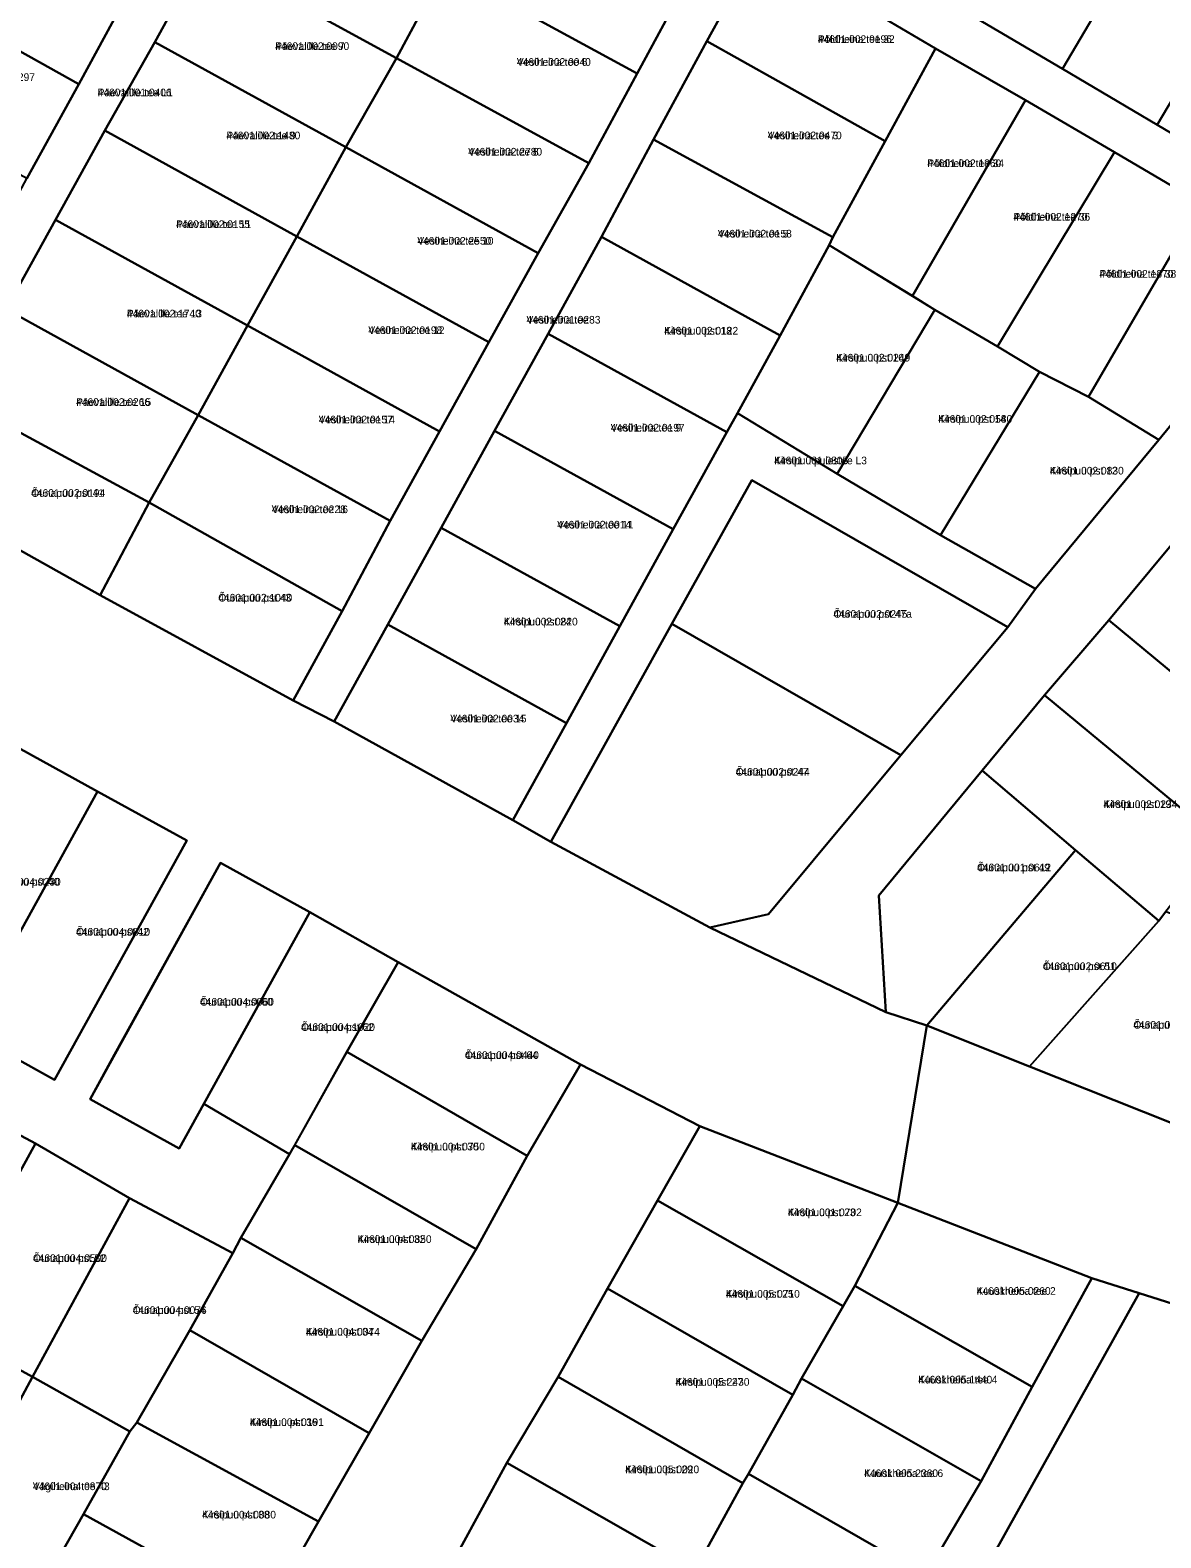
# Model space of a CAD drawing. Extents: x 551843 to 558501, y 6589003 to 6595718.
# Drawn here: x 552623.4 to 552845.1, y 6593188.1 to 6593483.8 of the extents above; entities that cross this region are included whole.
import ezdxf

# ---------------------------------------------------------------- set-up
doc = ezdxf.new("R2010")
doc.units = 0
for name, color, linetype in [('L_AADRESS', 7, 'Continuous'), ('PIIR', 7, 'Continuous'), ('TUNNUS', 7, 'Continuous')]:
    doc.layers.add(name, color=color, linetype=linetype)

msp = doc.modelspace()

# ---------------------------------------------------------------- linework, layer by layer
at = {"layer": 'PIIR'}
for points in [[(552660.92, 6593544.41), (552681.3, 6593543.01), (552676.56, 6593534.11), (552667.17, 6593516.83), (552657.46, 6593498.94), (552647.84, 6593481.41), (552638.03, 6593464.12), (552628.37, 6593446.6), (552618.71, 6593429.08), (552609.04, 6593411.57), (552599.39, 6593394.06), (552591.99, 6593398.44), (552602.33, 6593417.19), (552612.65, 6593435.92), (552622.77, 6593454.66), (552632.95, 6593473.18), (552643.15, 6593492.04), (552653.7, 6593510.58), (552664.72, 6593530.92)], [(552846.41, 6593511.09), (552825.8, 6593476.22), (552806.82, 6593487.36), (552827.29, 6593521.85)], [(552667.17, 6593516.83), (552704.66, 6593495.87), (552695.23, 6593478.3), (552657.46, 6593498.94)], [(552607.91, 6593511.51), (552643.15, 6593492.04), (552632.95, 6593473.18), (552597.6, 6593492.97)], [(552742.42, 6593475.29), (552704.66, 6593495.87), (552714.46, 6593513.43), (552751.91, 6593492.86)], [(552865.01, 6593500.1), (552844.4, 6593465.23), (552825.8, 6593476.22), (552846.41, 6593511.09), (552847.08, 6593510.72)], [(552751.91, 6593492.86), (552758.88, 6593505.25), (552766.49, 6593500.52), (552756.06, 6593481.6), (552745.63, 6593462.31), (552735.44, 6593443.26), (552724.97, 6593424.24), (552714.47, 6593405.23), (552703.99, 6593386.21), (552693.51, 6593367.19), (552683.03, 6593348.18), (552674.95, 6593352.34), (552684.6, 6593369.82), (552693.98, 6593387.52), (552703.66, 6593405.04), (552713.32, 6593422.59), (552723.01, 6593440.07), (552732.91, 6593457.71), (552742.42, 6593475.29)], [(552756.06, 6593481.6), (552766.49, 6593500.52), (552800.91, 6593480.16), (552791.04, 6593462.01)], [(552844.4, 6593465.23), (552865.01, 6593500.1), (552883.61, 6593489.1), (552862.75, 6593454.33)], [(552657.46, 6593498.94), (552695.23, 6593478.3), (552685.33, 6593460.85), (552647.84, 6593481.41)], [(552742.42, 6593475.29), (552732.91, 6593457.71), (552695.23, 6593478.3), (552704.66, 6593495.87)], [(552597.6, 6593492.97), (552632.95, 6593473.18), (552622.77, 6593454.66), (552587.23, 6593474.17), (552592.89, 6593484.72)], [(552745.63, 6593462.31), (552756.06, 6593481.6), (552791.04, 6593462.01), (552780.81, 6593443.17)], [(552685.33, 6593460.85), (552675.66, 6593443.34), (552638.03, 6593464.12), (552647.84, 6593481.41)], [(552780.03, 6593441.62), (552780.81, 6593443.17), (552791.04, 6593462.01), (552800.91, 6593480.16), (552818.57, 6593470.07), (552796.41, 6593431.66)], [(552695.23, 6593478.3), (552732.91, 6593457.71), (552723.01, 6593440.07), (552685.33, 6593460.85)], [(552835.98, 6593459.84), (552813.09, 6593421.74), (552800.81, 6593428.95), (552796.41, 6593431.66), (552818.57, 6593470.07)], [(552638.03, 6593464.12), (552675.66, 6593443.34), (552666.01, 6593425.83), (552628.37, 6593446.6)], [(552723.01, 6593440.07), (552713.32, 6593422.59), (552675.66, 6593443.34), (552685.33, 6593460.85)], [(552745.63, 6593462.31), (552780.81, 6593443.17), (552780.03, 6593441.62), (552770.48, 6593423.92), (552735.44, 6593443.26)], [(552853.01, 6593449.87), (552830.93, 6593411.86), (552821.29, 6593416.75), (552813.09, 6593421.74), (552835.98, 6593459.84)], [(552873.04, 6593438.03), (552844.73, 6593403.44), (552830.93, 6593411.86), (552853.01, 6593449.87)], [(552628.37, 6593446.6), (552666.01, 6593425.83), (552656.34, 6593408.3), (552618.71, 6593429.08)], [(552713.32, 6593422.59), (552703.66, 6593405.04), (552666.01, 6593425.83), (552675.66, 6593443.34)], [(552770.48, 6593423.92), (552762.08, 6593408.7), (552759.99, 6593404.91), (552724.97, 6593424.24), (552735.44, 6593443.26)], [(552781.62, 6593396.74), (552762.08, 6593408.7), (552770.48, 6593423.92), (552780.03, 6593441.62), (552800.81, 6593428.95)], [(552656.34, 6593408.3), (552646.71, 6593391.12), (552609.04, 6593411.57), (552618.71, 6593429.08)], [(552781.62, 6593396.74), (552800.81, 6593428.95), (552813.09, 6593421.74), (552821.29, 6593416.75), (552801.92, 6593384.73)], [(552693.98, 6593387.52), (552656.34, 6593408.3), (552666.01, 6593425.83), (552703.66, 6593405.04)], [(552714.47, 6593405.23), (552724.97, 6593424.24), (552759.99, 6593404.91), (552749.49, 6593385.9)], [(552820.54, 6593374.19), (552801.92, 6593384.73), (552821.29, 6593416.75), (552830.93, 6593411.86), (552844.73, 6593403.44)], [(552599.39, 6593394.06), (552609.04, 6593411.57), (552646.71, 6593391.12), (552637.14, 6593372.95)], [(552656.34, 6593408.3), (552693.98, 6593387.52), (552684.6, 6593369.82), (552646.71, 6593391.12)], [(552759.99, 6593404.91), (552762.08, 6593408.7), (552781.62, 6593396.74), (552801.92, 6593384.73), (552820.54, 6593374.19), (552815.08, 6593366.72), (552764.9, 6593395.51), (552749.24, 6593367.35), (552725.49, 6593324.63), (552718.05, 6593328.85), (552728.54, 6593347.87), (552739.03, 6593366.88), (552749.49, 6593385.9)], [(552714.47, 6593405.23), (552749.49, 6593385.9), (552739.03, 6593366.88), (552703.99, 6593386.21)], [(552764.9, 6593395.51), (552815.08, 6593366.72), (552794.14, 6593341.59), (552749.24, 6593367.35)], [(552684.6, 6593369.82), (552674.95, 6593352.34), (552637.14, 6593372.95), (552646.71, 6593391.12)], [(552703.99, 6593386.21), (552739.03, 6593366.88), (552728.54, 6593347.87), (552693.51, 6593367.19)], [(552881.45, 6593353.97), (552877.67, 6593349.36), (552869.6, 6593339.34), (552834.92, 6593368.05), (552847.11, 6593382.78)], [(552728.54, 6593347.87), (552718.05, 6593328.85), (552683.03, 6593348.18), (552693.51, 6593367.19)], [(552749.24, 6593367.35), (552794.14, 6593341.59), (552768.15, 6593310.4), (552756.64, 6593307.81), (552725.49, 6593324.63)], [(552834.92, 6593368.05), (552869.6, 6593339.34), (552856.94, 6593324.66), (552822.25, 6593353.36)], [(552810.06, 6593338.62), (552822.25, 6593353.36), (552856.94, 6593324.66), (552846.1, 6593310.91), (552844.71, 6593309.11), (552828.37, 6593322.95)], [(552608.23, 6593325.27), (552619.09, 6593344.16), (552636.6, 6593334.49), (552610.7, 6593287.57), (552593.19, 6593297.23), (552598.46, 6593306.95)], [(552799.23, 6593288.6), (552791.2, 6593291.19), (552789.78, 6593314.1), (552810.06, 6593338.62), (552828.37, 6593322.95)], [(552610.7, 6593287.57), (552636.6, 6593334.49), (552654.11, 6593324.83), (552628.2, 6593277.92)], [(552799.23, 6593288.6), (552828.37, 6593322.95), (552844.71, 6593309.11), (552819.32, 6593280.52)], [(552678.26, 6593310.83), (552657.48, 6593273.2), (552652.65, 6593264.45), (552635.14, 6593274.12), (552639.97, 6593282.86), (552660.75, 6593320.5)], [(552695.55, 6593301), (552685.47, 6593283.42), (552674.28, 6593263.36), (552657.48, 6593273.2), (552678.26, 6593310.83)], [(552819.32, 6593280.52), (552844.71, 6593309.11), (552846.1, 6593310.91), (552860.07, 6593305.95), (552847.12, 6593269.52)], [(552731.28, 6593280.95), (552720.86, 6593263.03), (552685.47, 6593283.42), (552695.55, 6593301)], [(552685.47, 6593283.42), (552720.86, 6593263.03), (552710.85, 6593244.74), (552675.28, 6593265.11)], [(552624.44, 6593265.44), (552605.01, 6593230), (552586.29, 6593240.49), (552605.17, 6593275.73)], [(552785.08, 6593237.53), (552782.8, 6593233.53), (552746.39, 6593254.25), (552754.7, 6593268.85), (552793.5, 6593253.79)], [(552605.01, 6593230), (552624.44, 6593265.44), (552642.91, 6593254.69), (552623.85, 6593219.65)], [(552675.28, 6593265.11), (552710.85, 6593244.74), (552700.22, 6593226.77), (552664.71, 6593246.94), (552674.28, 6593263.36)], [(552642.91, 6593254.69), (552663.17, 6593243.91), (552654.68, 6593228.8), (552644.33, 6593210.72), (552642.95, 6593208.95), (552623.85, 6593219.65)], [(552736.63, 6593237.01), (552746.39, 6593254.25), (552782.8, 6593233.53), (552774.63, 6593219.35), (552772.92, 6593216.16)], [(552785.08, 6593237.53), (552793.5, 6593253.79), (552831.56, 6593239.02), (552819.89, 6593217.73)], [(552664.71, 6593246.94), (552700.22, 6593226.77), (552689.9, 6593208.6), (552654.68, 6593228.8), (552663.17, 6593243.91)], [(552736.63, 6593237.01), (552772.92, 6593216.16), (552764.24, 6593200.63), (552763.13, 6593198.84), (552726.95, 6593219.7)], [(552774.63, 6593219.35), (552782.8, 6593233.53), (552785.08, 6593237.53), (552819.89, 6593217.73), (552809.88, 6593199.24)], [(552807.46, 6593176.14), (552840.87, 6593236.09), (552974.33, 6593193.77)], [(552604.93, 6593184.4), (552585.36, 6593194.77), (552605.01, 6593230), (552623.85, 6593219.65)], [(552654.68, 6593228.8), (552689.9, 6593208.6), (552679.92, 6593191.28), (552644.33, 6593210.72)], [(552604.93, 6593184.4), (552623.85, 6593219.65), (552642.95, 6593208.95), (552633.87, 6593192.76), (552623.45, 6593174.45)], [(552763.13, 6593198.84), (552754.26, 6593182.64), (552753.54, 6593181.86), (552716.86, 6593202.78), (552726.95, 6593219.7)], [(552772.92, 6593216.16), (552774.63, 6593219.35), (552809.88, 6593199.24), (552798.93, 6593180.69), (552764.24, 6593200.63)], [(552644.33, 6593210.72), (552679.92, 6593191.28), (552669.58, 6593173.09), (552633.87, 6593192.76), (552642.95, 6593208.95)], [(552716.86, 6593202.78), (552753.54, 6593181.86), (552743.84, 6593164.53), (552707.32, 6593185.27)], [(552763.13, 6593198.84), (552764.24, 6593200.63), (552798.93, 6593180.69), (552788.77, 6593162.59), (552754.26, 6593182.64)], [(552659.45, 6593154.58), (552623.45, 6593174.45), (552633.87, 6593192.76), (552669.58, 6593173.09)]]:
    msp.add_lwpolyline(points, close=True, dxfattribs=at)
for points in [[(552853.01, 6593449.87), (552835.98, 6593459.84), (552818.57, 6593470.07), (552800.91, 6593480.16), (552766.49, 6593500.52)], [(552806.82, 6593487.36), (552825.8, 6593476.22), (552844.4, 6593465.23), (552862.75, 6593454.33)], [(552847.11, 6593382.78), (552834.92, 6593368.05), (552822.25, 6593353.36), (552810.06, 6593338.62), (552789.78, 6593314.1), (552791.2, 6593291.19), (552756.64, 6593307.81), (552768.15, 6593310.4), (552794.14, 6593341.59), (552815.08, 6593366.72), (552820.54, 6593374.19), (552844.73, 6593403.44), (552873.04, 6593438.03)], [(552599.39, 6593394.06), (552637.14, 6593372.95), (552674.95, 6593352.34), (552683.03, 6593348.18), (552718.05, 6593328.85), (552725.49, 6593324.63), (552756.64, 6593307.81), (552791.2, 6593291.19), (552799.23, 6593288.6), (552793.5, 6593253.79), (552754.7, 6593268.85), (552731.28, 6593280.95), (552695.55, 6593301), (552678.26, 6593310.83), (552660.75, 6593320.5), (552635.14, 6593274.12), (552652.65, 6593264.45), (552657.48, 6593273.2), (552674.28, 6593263.36), (552664.71, 6593246.94), (552663.17, 6593243.91), (552642.91, 6593254.69), (552624.44, 6593265.44), (552605.17, 6593275.73)], [(552610.7, 6593287.57), (552628.2, 6593277.92), (552654.11, 6593324.83), (552636.6, 6593334.49), (552619.09, 6593344.16)], [(552974.33, 6593193.77), (552840.87, 6593236.09), (552831.56, 6593239.02), (552793.5, 6593253.79), (552799.23, 6593288.6), (552819.32, 6593280.52), (552847.12, 6593269.52)], [(552669.58, 6593173.09), (552679.92, 6593191.28), (552689.9, 6593208.6), (552700.22, 6593226.77), (552710.85, 6593244.74), (552720.86, 6593263.03), (552731.28, 6593280.95), (552754.7, 6593268.85), (552746.39, 6593254.25), (552736.63, 6593237.01), (552726.95, 6593219.7), (552716.86, 6593202.78), (552707.32, 6593185.27)], [(552798.93, 6593180.69), (552809.88, 6593199.24), (552819.89, 6593217.73), (552831.56, 6593239.02), (552840.87, 6593236.09), (552807.46, 6593176.14), (552974.33, 6593193.77), (552998.09, 6593186.23)]]:
    msp.add_lwpolyline(points, dxfattribs=at)

# ---------------------------------------------------------------- texts
at = {"layer": 'L_AADRESS'}
for s, p in [('Päevalille tee 7', (552671.46, 6593479.9)), ('Põldheina tee 32', (552777.85, 6593481.27)), ('Vesiheina tee 6', (552718.83, 6593476.79)), ('Päevalille tee L1', (552636.64, 6593470.81)), ('Päevalille tee 9', (552661.87, 6593462.38)), ('Vesiheina tee 3', (552768.02, 6593462.39)), ('Vesiheina tee 8', (552709.28, 6593459.19)), ('Põldheina tee 34', (552799.3, 6593456.93)), ('Päevalille tee 11', (552652.01, 6593444.98)), ('Põldheina tee 36', (552816.19, 6593446.43)), ('Vesiheina tee 10', (552699.31, 6593441.72)), ('Vesiheina tee 5', (552758.24, 6593443.12)), ('Põldheina tee 38', (552833.05, 6593435.24)), ('Päevalille tee 13', (552642.37, 6593427.45)), ('Vesiheina tee 12', (552689.7, 6593424.19)), ('Vesiheina tee', (552720.72, 6593426.24)), ('Kirsipuu pst 18', (552747.72, 6593424.09)), ('Kirsipuu pst 16', (552781.45, 6593418.8)), ('Päevalille tee 15', (552632.41, 6593410.1)), ('Vesiheina tee 14', (552679.99, 6593406.67)), ('Kirsipuu pst 14', (552801.45, 6593406.79)), ('Vesiheina tee 9', (552737.23, 6593405.07)), ('Kirsipuu puiestee L3', (552769.29, 6593398.64)), ('Kirsipuu pst 12', (552823.32, 6593396.64)), ('Õunapuu pst 41', (552623.61, 6593392.26)), ('Vesiheina tee 16', (552670.78, 6593389.06)), ('Vesiheina tee 11', (552726.74, 6593386.05)), ('Õunapuu pst 43', (552660.29, 6593371.73)), ('Õunapuu pst 47a', (552780.9, 6593368.55)), ('Kirsipuu pst 24', (552716.26, 6593367.04)), ('Vesiheina tee 15', (552705.79, 6593348.02)), ('Õunapuu pst 47', (552761.74, 6593337.58)), ('Kirsipuu pst 19', (552833.84, 6593331.24)), ('Õunapuu pst 49', (552809.07, 6593318.82)), ('Õunapuu pst 40', (552614.89, 6593316.02)), ('Õunapuu pst 42', (552632.41, 6593306.21)), ('Õunapuu pst 51', (552821.97, 6593299.45)), ('Õunapuu pst 60', (552656.7, 6593292.48)), ('Õunapuu pst 62', (552676.51, 6593287.52)), ('Õunapuu pst 53', (552839.7, 6593287.96)), ('Õunapuu pst 64', (552708.65, 6593282.02)), ('Kirsipuu pst 30', (552698.06, 6593264.08)), ('Kirsipuu pst 23', (552771.96, 6593251.19)), ('Kirsipuu pst 32', (552687.61, 6593245.94)), ('Õunapuu pst 52', (552623.96, 6593242.21)), ('Kirsipuu pst 25', (552759.81, 6593235.21)), ('Kuuskheina tee 2', (552808.98, 6593235.76)), ('Õunapuu pst 54', (552643.51, 6593232.02)), ('Kirsipuu pst 34', (552677.47, 6593227.77)), ('Kirsipuu pst 27', (552749.94, 6593217.93)), ('Kuuskheina tee 4', (552797.53, 6593218.38)), ('Kirsipuu pst 36', (552666.48, 6593210.04)), ('Kirsipuu pst 29', (552740.07, 6593200.78)), ('Kuuskheina tee 6', (552786.91, 6593200.02)), ('Vägiheina tee 43', (552623.94, 6593197.46)), ('Kirsipuu pst 38', (552657.1, 6593191.9))]:
    msp.add_text(s, height=1.5, dxfattribs=at).set_placement(p)
at = {"layer": 'TUNNUS'}
for s, p in [('44601:002:0196', (552777.85, 6593481.27)), ('44601:002:0090', (552671.46, 6593479.9)), ('44601:002:0040', (552718.83, 6593476.79)), ('44601:002:0297', (552609.85, 6593473.82)), ('44601:001:0406', (552636.64, 6593470.81)), ('44601:002:1480', (552661.87, 6593462.38)), ('44601:002:0470', (552768.02, 6593462.39)), ('44601:002:2780', (552709.28, 6593459.19)), ('44601:002:1360', (552799.3, 6593456.93)), ('44601:002:0155', (552652.01, 6593444.98)), ('44601:002:1270', (552816.19, 6593446.43)), ('44601:002:2550', (552699.31, 6593441.72)), ('44601:002:0158', (552758.24, 6593443.12)), ('44601:002:1370', (552833.05, 6593435.24)), ('44601:002:1740', (552642.37, 6593427.45)), ('44601:002:0198', (552689.7, 6593424.19)), ('44601:001:0283', (552720.72, 6593426.24)), ('44601:002:0122', (552747.72, 6593424.09)), ('44601:002:0249', (552781.45, 6593418.8)), ('44601:002:0266', (552632.41, 6593410.1)), ('44601:002:0157', (552679.99, 6593406.67)), ('44601:002:0580', (552801.45, 6593406.79)), ('44601:002:0197', (552737.23, 6593405.07)), ('44601:001:0805', (552769.29, 6593398.64)), ('44601:002:0830', (552823.32, 6593396.64)), ('44601:002:0194', (552623.61, 6593392.26)), ('44601:002:0228', (552670.78, 6593389.06)), ('44601:002:0014', (552726.74, 6593386.05)), ('44601:002:1040', (552660.29, 6593371.73)), ('44601:002:0245', (552780.9, 6593368.55)), ('44601:002:0820', (552716.26, 6593367.04)), ('44601:002:0034', (552705.79, 6593348.02)), ('44601:002:0244', (552761.74, 6593337.58)), ('44601:002:0234', (552833.84, 6593331.24)), ('44601:001:0612', (552809.07, 6593318.82)), ('44601:004:0230', (552614.89, 6593316.02)), ('44601:004:0810', (552632.41, 6593306.21)), ('44601:002:0610', (552821.97, 6593299.45)), ('44601:004:0060', (552656.7, 6593292.48)), ('44601:002:2340', (552839.7, 6593287.96)), ('44601:004:1020', (552676.51, 6593287.52)), ('44601:004:0440', (552708.65, 6593282.02)), ('44601:004:0750', (552698.06, 6593264.08)), ('44601:001:0702', (552771.96, 6593251.19)), ('44601:004:0850', (552687.61, 6593245.94)), ('44601:004:0500', (552623.96, 6593242.21)), ('44601:005:0710', (552759.81, 6593235.21)), ('44601:005:0260', (552808.98, 6593235.76)), ('44601:004:0076', (552643.51, 6593232.02)), ('44601:004:0074', (552677.47, 6593227.77)), ('44601:005:2430', (552749.94, 6593217.93)), ('44601:005:1440', (552797.53, 6593218.38)), ('44601:004:0191', (552666.48, 6593210.04)), ('44601:005:0020', (552740.07, 6593200.78)), ('44601:005:2360', (552786.91, 6593200.02)), ('44601:004:0870', (552623.94, 6593197.46)), ('44601:004:0080', (552657.1, 6593191.9))]:
    msp.add_text(s, height=1.5, dxfattribs=at).set_placement(p)

doc.saveas('drawing.dxf')
